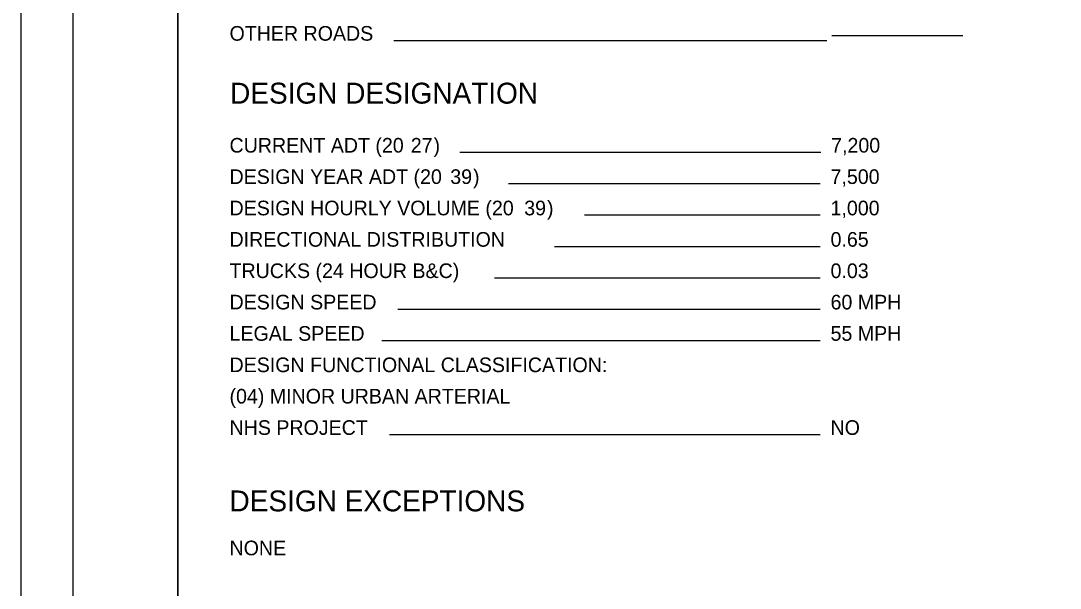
# Model space of a CAD drawing. Extents: x 0 to 34, y 0 to 22.
# Drawn here: x 0 to 9.93, y 5.64 to 11.07 of the extents above; entities that cross this region are included whole.
import ezdxf

# ---------------------------------------------------------------- set-up
doc = ezdxf.new("R2010")
doc.units = 0
for name, color, linetype in [('SH_Border', 7, 'Continuous'), ('SH_Cut_Line', 7, 'Continuous'), ('SH_Data', 7, 'Continuous'), ('SH_Text', 7, 'Continuous')]:
    doc.layers.add(name, color=color, linetype=linetype)

msp = doc.modelspace()

# ---------------------------------------------------------------- linework, layer by layer
at = {"layer": 'SH_Border'}
for points in [[(0.5, 21.5), (1.5, 21.5), (1.5, 0.5), (0.5, 0.5)], [(1.5, 21.5), (33.5, 21.5), (33.5, 0.5), (1.5, 0.5)]]:
    msp.add_lwpolyline(points, close=True, dxfattribs=at)
at = {"layer": 'SH_Cut_Line'}
msp.add_lwpolyline([(0, 0), (34, 0), (34, 22), (0, 22)], close=True, dxfattribs=at)
at = {"layer": 'SH_Data'}
for p, q in [((7.7, 10.8767), (3.5657, 10.8767)), ((9, 10.9223), (7.75, 10.9223)), ((7.6424, 9.8062), (4.1936, 9.8062)), ((7.6368, 9.5062), (4.6592, 9.5062)), ((7.6368, 9.2062), (5.3852, 9.2062)), ((7.6368, 8.9062), (5.0988, 8.9062)), ((7.6368, 8.6062), (4.5259, 8.6062)), ((7.6368, 8.3062), (3.6035, 8.3062)), ((7.6368, 8.0062), (3.4488, 8.0062)), ((7.6368, 7.1062), (3.5243, 7.1062))]:
    msp.add_line(p, q, dxfattribs=at)

# ---------------------------------------------------------------- texts
msp.add_text('DESIGN DESIGNATION', height=0.2, dxfattribs=at).set_placement((2, 10.2747))
at = {"layer": 'SH_Text'}
for s, height, p in [('OTHER ROADS', 0.14, (1.9944, 10.8767)), ('CURRENT ADT (20', 0.14, (1.9944, 9.8062)), ('27', 0.14, (3.7261, 9.8062)), (')', 0.14, (3.9435, 9.8062)), ('7,200 ', 0.14, (7.7424, 9.8062)), ('DESIGN YEAR ADT (20', 0.14, (1.9944, 9.5062)), ('39', 0.14, (4.1033, 9.5062)), (')', 0.14, (4.3207, 9.5062)), ('7,500 ', 0.14, (7.7368, 9.5062)), ('DESIGN HOURLY VOLUME (20', 0.14, (1.9944, 9.2062)), ('39', 0.14, (4.8099, 9.2062)), (')', 0.14, (5.0274, 9.2062)), ('1,000 ', 0.14, (7.7368, 9.2062)), ('DIRECTIONAL DISTRIBUTION', 0.14, (1.9944, 8.9062)), ('0.65  ', 0.14, (7.7368, 8.9062)), ('TRUCKS (24 HOUR B&C)', 0.14, (1.9944, 8.6062)), ('0.03  ', 0.14, (7.7368, 8.6062)), ('DESIGN SPEED', 0.14, (1.9944, 8.3062)), ('60 MPH', 0.14, (7.7368, 8.3062)), ('LEGAL SPEED', 0.14, (1.9944, 8.0062)), ('55 MPH', 0.14, (7.7368, 8.0062)), ('DESIGN FUNCTIONAL CLASSIFICATION:', 0.14, (1.9944, 7.7062)), ('(04) MINOR URBAN ARTERIAL                       ', 0.14, (1.9944, 7.4062)), ('NHS PROJECT', 0.14, (1.9944, 7.1062)), ('NO', 0.14, (7.7368, 7.1062)), ('DESIGN EXCEPTIONS', 0.2, (1.9944, 6.3744)), ('NONE', 0.14, (1.9944, 5.9544))]:
    msp.add_text(s, height=height, dxfattribs=at).set_placement(p)

doc.saveas('drawing.dxf')
